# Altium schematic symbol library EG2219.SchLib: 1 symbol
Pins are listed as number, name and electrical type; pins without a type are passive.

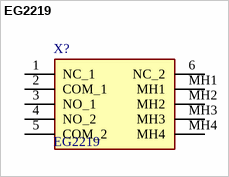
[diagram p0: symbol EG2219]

## EG2219
designator X?
SLIDE, 500mA, 15VDC DPDT, On-On Through Hole, Right Angle; Manufacturer_Name: E-Switch; Geometry.Height: 8.5mm
footprint EG2219
pins: 1 NC_1, 2 COM_1, 3 NO_1, 4 NO_2, 5 COM_2, 6 NC_2, MH1, MH2, MH3, MH4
